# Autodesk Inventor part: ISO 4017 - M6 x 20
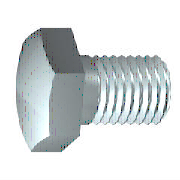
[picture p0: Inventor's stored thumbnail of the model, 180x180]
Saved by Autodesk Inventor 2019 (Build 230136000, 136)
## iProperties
Created: 2018-01
Part Number: ISO 4017 - M6 x 20
Material: Acier inoxydable 440C
Description: Vis à tête hexagonale
Document SubType Name: Modeling
Standard: ISO 4017
Designer: Thier
Standard Revision: Fourth edition 2011-04-01
Standards Organization: ISO
Language: fr-FR
Size Designation: M6 x 20
Categories: <MemberInstance><Categories><Category DisplayName="Visserie" InternalName="e4da775c-781d-43d5-af7c-5136215cf5a6" Mnemonic="FSTN"><Category DisplayName="Vis" Int
Density: 7.75 g/cm^3
Appearance: Semi-poli
IsCustomPart: 0
Author: Thier
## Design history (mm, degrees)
sketch "Esquisse1"
  geometry: L1 (0, 4.44)-(0, 3); L2 (3, 3)-(20, 3); L3 (20, 3)-(20, 0); L4 (20, 0)-(-0.5, 0); L5 (-4.6, 0)-(24.1, 0) reference; L6 (-0.5, 0)-(-0.5, 4.44); L7 (-0.5, 4.44)-(0, 4.44); L8 (3, 3)-(2.386, 3); L9 (2.386, 3)-(0, 3); L10 (0, -0.888)-(0, 5.328) reference
  constraints: 16 end point, 2 collinear, 2 perpendicular, 1 parallel
  dimensions: "d0" = 20 distance between parallel lines of L3 L1 (= NLG); "d1" = 17 distance from line of L2.start L3 (= GEL); "d2" = 6 diameter of L2 L4 (= GD); "d9" = 0.5001 distance between parallel lines of L6 L1 (computed from SD); "d10" = 8.88 diameter of L7 L4 (= SD2); "d13" = 0.61355 distance of L2.start L8.end (computed from GAL); "d14" = 6 diameter of L9 L4 (= BDM)
revolve "Corps" sketch "Esquisse1" stored, may be unused: angle "d12" = 90 deg
sketch "Esquisse2"
  geometry: L1 (0, 5.774)-(5, 2.887); L2 (5, 2.887)-(5, -2.887); L3 (5, -2.887)-(0, -5.774); L4 (0, -5.774)-(-5, -2.887); L5 (-5, -2.887)-(-5, 2.887); L6 (-5, 2.887)-(0, 5.774); 2 further points
  constraints: 12 end point, 1 coincident, 1 vertical, 11 other
  dimensions: "d11" = 10 distance between parallel lines of L5 L2 (= SW)
extrude "Tête" join sketch "Esquisse2" distance "d3" = 3.5 (= KOH - SD); taper "d4" = 0 deg
sketch "Esquisse4"
  geometry: L1 (-4, 5)-(-4, 5.774); L2 (-4, 5.774)-(-3.554, 5.774); L3 (-3.554, 5.774)-(-4, 5); L4 (-4.7, 0)-(0.2, 0) reference; L5 (-0.5, 5.774)-(-4, 5.774) reference; L6 (-4, 2.887)-(-4, 5.774) reference
  constraints: 6 end point, 2 collinear, 1 perpendicular, 1 vertical
  dimensions: "d5" = 30 deg angle of L3 L1 (= ANG1); "d19" = 10 diameter of L1.start L4 (= SW0)
revolve "Chanfrein1" sketch "Esquisse4" stored, may be unused: angle "d21" = 90 deg
workplane "Work Plane1"
body "Solid1"
feature "Filetage" dims "d15" = 17 (= GEL), "d16" = 0
chamfer "Chanfrein2" distance "d6" = 0.61345 (= -0.5 x SPD + 0.5 x GD); stored, may be unused: second distance "d7" = 0.61355 (computed from GUL), angle "d55" = 45 deg
other parameters: "NLG" = 20 [user parameter; used in 1 equation term], "GD" = 6 (= NND) [user parameter; used in 2 equation terms], "BDM" = 6 (= NND) [user parameter; used in 1 equation term], "KOH" = 4 [user parameter; used in 1 equation term], "GEL" = 17 [user parameter; used in 2 equation terms], "SW" = 10 [user parameter; used in 2 equation terms], "SW0" = 10 (= SW) [user parameter; used in 1 equation term], "SPD" = 4.7731 (= NND - 1.2269 x PTC) [user parameter; used in 1 equation term], "SD2" = 8.88 [user parameter; used in 2 equation terms], "SD" = 0.5 [user parameter; used in 2 equation terms], "ANG1" = 30 deg [user parameter; used in 1 equation term], "GAL" = 0.61345 (= 0.61345 x PTC) [user parameter; used in 1 equation term], "GUL" = 0.61345 (= 0.61345 x PTC) [user parameter; used in 1 equation term], "d8" = 0, "RR" = 0.25 [user parameter], "d57" = 0, "d58" = 0, "GD1" = 4.7731 (= THREADDIA - 1.2269 x PTC) [user parameter], "THREADDIA" = 6 [user parameter; used in 1 equation term], "SDH" = 8.88 (= SD2) [user parameter], "SDHG" = 3 [user parameter], "TOA" = 30 deg [user parameter], "PTC" = 1 [user parameter; used in 5 equation terms], "NND" = 6 [user parameter; used in 3 equation terms], "E0" = 11.55 [user parameter]
